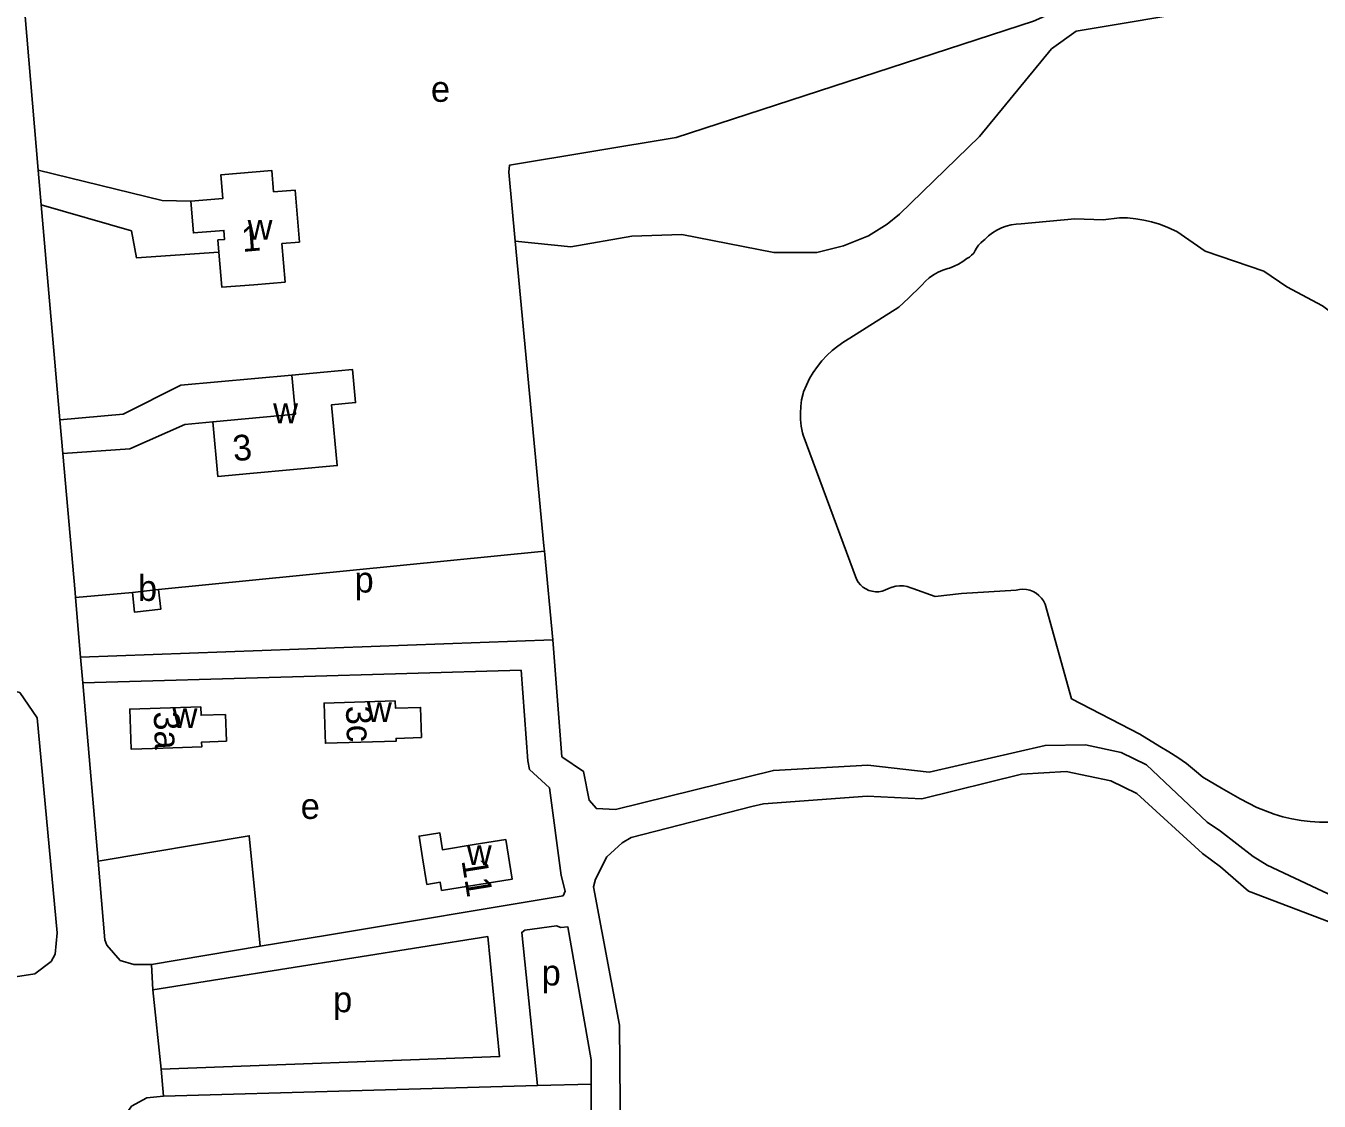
# Model space of a CAD drawing. Extents: x 162667 to 164645, y 379003 to 382150.
# Drawn here: x 163114.4 to 163315.3, y 380520.8 to 380688 of the extents above; entities that cross this region are included whole.
import ezdxf

# ---------------------------------------------------------------- set-up
doc = ezdxf.new("R2010")
doc.units = 0
for name, color, linetype in [('BLT_Basislijn', 7, 'Continuous'), ('BLT_Bebouwing', 7, 'Continuous'), ('BLT_Centroide', 7, 'Continuous'), ('BLT_Huisnummer', 7, 'Continuous')]:
    doc.layers.add(name, color=color, linetype=linetype)

msp = doc.modelspace()

# ---------------------------------------------------------------- linework, layer by layer
at = {"layer": 'BLT_Basislijn'}
for p, q in [((163116.28, 380665.57), (163116.75, 380660.21)), ((163119.65, 380626.79), (163116.75, 380660.21)), ((163242.42, 380639.46), (163250.05, 380644.27)), ((163120.1, 380621.54), (163119.65, 380626.79)), ((163235.14, 380624.38), (163243.46, 380602)), ((163135, 380600.37), (163194.97, 380606.34)), ((163196.24, 380592.59), (163194.97, 380606.34)), ((163130.92, 380599.93), (163122.08, 380599.13)), ((163122.08, 380599.13), (163122.85, 380589.89)), ((163122.85, 380589.89), (163196.24, 380592.59)), ((163122.85, 380589.89), (163123.22, 380585.86)), ((163191.34, 380587.84), (163155.8, 380586.81)), ((163192.4, 380573.74), (163191.34, 380587.84)), ((163125.59, 380558.18), (163123.22, 380585.86)), ((163287.47, 380577.88), (163290.59, 380575.99)), ((163192.65, 380572.42), (163192.4, 380573.74)), ((163195.75, 380569.58), (163192.65, 380572.42)), ((163197.56, 380555.95), (163195.75, 380569.58)), ((163126.64, 380545.94), (163125.59, 380558.18)), ((163198.2, 380553.5), (163197.56, 380555.95)), ((163161.24, 380546.66), (163197.88, 380552.76)), ((163197.88, 380552.76), (163198.2, 380553.5)), ((163126.96, 380545.08), (163126.64, 380545.94)), ((163129.03, 380542.69), (163126.96, 380545.08)), ((163131.13, 380542.07), (163129.03, 380542.69)), ((163133.87, 380542.11), (163131.13, 380542.07)), ((163133.87, 380542.11), (163134.12, 380538.17)), ((163135.38, 380525.83), (163134.12, 380538.17)), ((163135.75, 380521.6), (163135.38, 380525.83)), ((163135.75, 380521.6), (163193.9, 380523.28)), ((163202.23, 380523.49), (163193.9, 380523.28))]:
    msp.add_line(p, q, dxfattribs=at)
for points in [[(163116.28, 380665.57), (163112.77, 380707.3), (163114.27, 380709.01), (163147.61, 380711.21), (163185.6, 380714.88), (163208.39, 380718.9), (163230.08, 380724.48), (163246.33, 380729.8), (163260.42, 380735.06), (163271.22, 380739.44), (163282.17, 380744.37), (163282.98, 380744.48), (163295.56, 380751.32), (163300, 380754.05), (163310.75, 380759.91), (163318.6, 380764.96)], [(163338.76, 380722.04), (163315.86, 380708.61), (163315.6, 380708.61), (163270.98, 380688.76), (163215.44, 380670.68), (163189.52, 380666.35), (163189.4, 380665.27), (163190.4, 380654.55)], [(163337.81, 380688.96), (163325.86, 380690.6), (163305.09, 380695.32), (163300, 380691.92), (163298.34, 380690.69), (163277.61, 380687.22), (163273.78, 380684.45), (163262.57, 380670.81), (163250.14, 380658.76), (163248.22, 380657.17), (163245.33, 380655.39), (163241.42, 380653.81), (163237.29, 380652.8), (163230.63, 380652.8), (163216.29, 380655.6), (163208.55, 380655.35), (163199.05, 380653.68), (163190.4, 380654.55)], [(163140.01, 380660.75), (163135.56, 380660.86), (163116.28, 380665.57)], [(163144.38, 380652.83), (163131.55, 380651.96), (163130.78, 380656.15), (163116.75, 380660.21)], [(163269.06, 380657.24), (163268.27, 380657.21), (163267.49, 380657.09), (163266.72, 380656.89), (163265.97, 380656.61), (163265.26, 380656.27), (163264.58, 380655.85), (163263.96, 380655.36), (163263.38, 380654.82), (163263.21, 380654.64)], [(163284.32, 380658.2), (163281.8, 380657.85), (163277.38, 380658.03), (163269.06, 380657.24)], [(163284.32, 380658.2), (163285.58, 380658.15), (163286.84, 380658.02), (163288.08, 380657.82), (163289.31, 380657.53), (163290.52, 380657.17), (163291.71, 380656.73), (163292.86, 380656.22), (163293.24, 380656.03)], [(163194.97, 380606.34), (163194.89, 380607.17), (163190.4, 380654.55)], [(163263.21, 380654.64), (163262.79, 380654.31), (163262.42, 380653.92), (163262.12, 380653.48), (163261.91, 380653.08)], [(163293.24, 380656.03), (163297.66, 380653), (163306.77, 380649.87), (163310.32, 380647.45), (163315.87, 380644.5), (163318.99, 380642.16), (163322.02, 380640.51), (163325.75, 380639.3), (163329.73, 380637.21), (163333.84, 380635.33)], [(163261.91, 380653.08), (163261.67, 380652.69), (163261.35, 380652.35), (163260.99, 380652.07), (163260.61, 380651.87)], [(163260.61, 380651.87), (163259.99, 380651.39), (163259.32, 380650.98), (163258.61, 380650.64), (163257.88, 380650.37), (163257.67, 380650.31)], [(163257.67, 380650.31), (163256.89, 380650.05), (163256.15, 380649.72), (163255.44, 380649.31), (163254.77, 380648.84), (163254.15, 380648.31), (163253.59, 380647.72), (163253.51, 380647.62)], [(163253.51, 380647.62), (163251.51, 380645.71), (163250.05, 380644.27)], [(163242.42, 380639.46), (163241.46, 380638.89), (163240.53, 380638.24), (163239.66, 380637.54), (163238.84, 380636.77), (163238.08, 380635.95), (163237.37, 380635.07), (163236.73, 380634.15), (163236.16, 380633.18), (163235.66, 380632.17), (163235.23, 380631.13), (163235.14, 380630.88)], [(163155.69, 380633.7), (163138.43, 380632.14), (163129.51, 380627.63), (163119.65, 380626.79)], [(163235.14, 380630.88), (163234.93, 380629.87), (163234.79, 380628.86), (163234.74, 380627.83), (163234.76, 380626.8), (163234.86, 380625.78), (163235.05, 380624.77), (163235.14, 380624.38)], [(163143.42, 380626.47), (163139.07, 380626.04), (163130.53, 380622.24), (163120.1, 380621.54)], [(163122.08, 380599.13), (163122.01, 380599.93), (163120.1, 380621.54)], [(163243.46, 380602), (163243.73, 380601.55), (163244.06, 380601.13), (163244.45, 380600.78), (163244.89, 380600.48), (163245.37, 380600.26), (163245.88, 380600.11), (163246.4, 380600.04), (163246.93, 380600.05), (163247.45, 380600.13), (163247.88, 380600.27)], [(163247.88, 380600.27), (163248.41, 380600.55), (163248.97, 380600.77), (163249.56, 380600.9), (163250.15, 380600.96), (163250.75, 380600.94), (163251.35, 380600.84), (163251.92, 380600.66), (163252.21, 380600.53)], [(163252.21, 380600.53), (163255.68, 380599.32), (163259.76, 380599.75), (163268.25, 380600.27)], [(163268.25, 380600.27), (163268.78, 380600.39), (163269.32, 380600.43), (163269.86, 380600.39), (163270.4, 380600.27), (163270.9, 380600.07), (163271.38, 380599.8), (163271.81, 380599.47), (163272.18, 380599.07), (163272.49, 380598.63), (163272.76, 380598.1)], [(163272.76, 380598.1), (163276.87, 380583.41), (163287.47, 380577.88)], [(163334.72, 380553.11), (163320.16, 380551.45), (163307.28, 380557.55), (163305.1, 380558.88), (163300, 380562.84), (163297.94, 380564.21), (163288.54, 380573.13), (163284.56, 380575.04), (163279.04, 380576.24), (163272.77, 380576.16), (163254.76, 380572.01), (163245.21, 380573.08), (163230.54, 380572.26), (163206, 380566.17), (163203.03, 380566.34), (163201.9, 380567.65), (163201.02, 380572.1), (163197.65, 380574.4), (163196.24, 380592.59)], [(163155.8, 380586.81), (163123.22, 380585.86)], [(163107.61, 380584.83), (163111.58, 380584.87), (163113.41, 380584.38), (163116.12, 380580.46), (163119.23, 380546.99), (163118.93, 380543.71), (163118.3, 380542.56), (163115.74, 380540.62), (163112.09, 380540.07)], [(163290.59, 380575.99), (163292.01, 380575.18), (163293.39, 380574.29), (163294.72, 380573.34), (163296, 380572.33), (163297.27, 380571.22)], [(163334.79, 380549.19), (163320.6, 380547.31), (163304.35, 380553.49), (163300, 380557.3), (163297.21, 380559.33), (163287.04, 380568.67), (163282.96, 380570.67), (163276.02, 380572.1), (163269.1, 380571.69), (163253.58, 380567.87), (163245.13, 380568.27), (163229.01, 380567.07), (163227.19, 380566.68), (163208.45, 380561.85), (163207.02, 380561.02), (163204.63, 380558.84), (163202.88, 380555.36), (163202.59, 380554.19), (163206.63, 380532.65), (163206.87, 380502.27)], [(163297.27, 380571.22), (163300.16, 380569.5), (163303.1, 380567.84), (163304.37, 380567.15)], [(163304.37, 380567.15), (163305.67, 380566.52), (163306.99, 380565.96), (163308.34, 380565.48), (163309.72, 380565.07), (163311.12, 380564.74), (163312.54, 380564.49), (163313.97, 380564.32), (163315.4, 380564.22), (163316.84, 380564.21), (163318.27, 380564.28), (163319.28, 380564.37)], [(163125.59, 380558.18), (163149.09, 380562.11), (163150.79, 380544.92)], [(163202.23, 380523.49), (163202.2, 380527.27), (163198.57, 380547.95), (163197.51, 380547.82), (163196.81, 380548.11), (163191.91, 380547.44), (163191.43, 380547.09), (163193.9, 380523.28)], [(163135.38, 380525.83), (163187.99, 380527.78), (163186.14, 380546.42), (163134.12, 380538.17)], [(163150.79, 380544.92), (163161.24, 380546.66)], [(163133.87, 380542.11), (163150.79, 380544.92)], [(163139.75, 380476.78), (163204.19, 380487.67), (163202.17, 380500.07), (163202.23, 380523.49)], [(163135.75, 380521.6), (163133.17, 380521.37), (163130.8, 380520.08), (163129.35, 380517.93), (163129.19, 380514.65), (163133.2, 380479.74), (163135.24, 380477.14), (163136.88, 380476.63), (163139.75, 380476.78)]]:
    msp.add_lwpolyline(points, dxfattribs=at)
at = {"layer": 'BLT_Bebouwing'}
for p, q in [((163130.92, 380599.93), (163135, 380600.37)), ((163145.41, 380580.97), (163145.54, 380576.8)), ((163176.03, 380558.67), (163176.69, 380554.54))]:
    msp.add_line(p, q, dxfattribs=at)
for points in [[(163144.38, 380652.83), (163144.84, 380647.37), (163149.82, 380647.78), (163154.66, 380648.19), (163154.16, 380654.17), (163156.89, 380654.4), (163156.21, 380662.5), (163152.87, 380662.22), (163152.6, 380665.51), (163144.67, 380664.85), (163144.98, 380661.16), (163140.01, 380660.75)], [(163140.01, 380660.75), (163140.42, 380655.84), (163145.14, 380656.23), (163145.26, 380654.83), (163144.22, 380654.75), (163144.38, 380652.83)], [(163155.69, 380633.7), (163160.67, 380634.16), (163165.14, 380634.58), (163165.62, 380629.46), (163161.89, 380629.11), (163162.76, 380619.67), (163149.18, 380618.41), (163144.21, 380617.95), (163143.42, 380626.47)], [(163143.42, 380626.47), (163156.25, 380627.65), (163155.69, 380633.7)], [(163135, 380600.37), (163135.33, 380597.31), (163131.25, 380596.88), (163130.92, 380599.93)], [(163175.87, 380577.37), (163171.91, 380577.24), (163171.92, 380576.83), (163160.92, 380576.48), (163160.88, 380577.74), (163160.72, 380582.74), (163171.76, 380583.08), (163171.79, 380581.95), (163175.72, 380582.07), (163175.87, 380577.37)], [(163145.54, 380576.8), (163141.68, 380576.68), (163141.7, 380575.91), (163135.71, 380575.73), (163130.71, 380575.57), (163130.51, 380581.8), (163141.55, 380582.15), (163141.59, 380580.85), (163145.41, 380580.97)], [(163176.69, 380554.54), (163178.76, 380554.89), (163178.97, 380553.61), (163189.95, 380555.38), (163188.95, 380561.52), (163184.02, 380560.73), (163179.11, 380559.94), (163178.68, 380562.57), (163175.48, 380562.05), (163176.03, 380558.67)]]:
    msp.add_lwpolyline(points, dxfattribs=at)

# ---------------------------------------------------------------- texts
at = {"layer": 'BLT_Centroide'}
for s, p in [('e', (163177.32, 380676.21)), ('w', (163148.83, 380654.78)), ('w', (163152.8, 380626.25)), ('b', (163131.79, 380598.62)), ('p', (163165.45, 380599.92)), ('w', (163167.38, 380579.78)), ('w', (163137.17, 380578.84)), ('e', (163157.08, 380564.72)), ('w', (163182.9, 380557.56)), ('p', (163194.52, 380538.83)), ('p', (163162.12, 380534.67))]:
    msp.add_text(s, height=4, dxfattribs=at).set_placement(p)
at = {"layer": 'BLT_Huisnummer'}
for s, rotation, p in [('1', 4.7852, (163148.03, 380652.87)), ('3', 5.2933, (163146.69, 380620.32)), ('3a', 271.7996, (163134.24, 380581.41)), ('3c', 271.7996, (163164.1, 380582.28)), ('11', 279.1591, (163182.06, 380558.26))]:
    msp.add_text(s, height=4, rotation=rotation, dxfattribs=at).set_placement(p)

doc.saveas('drawing.dxf')
